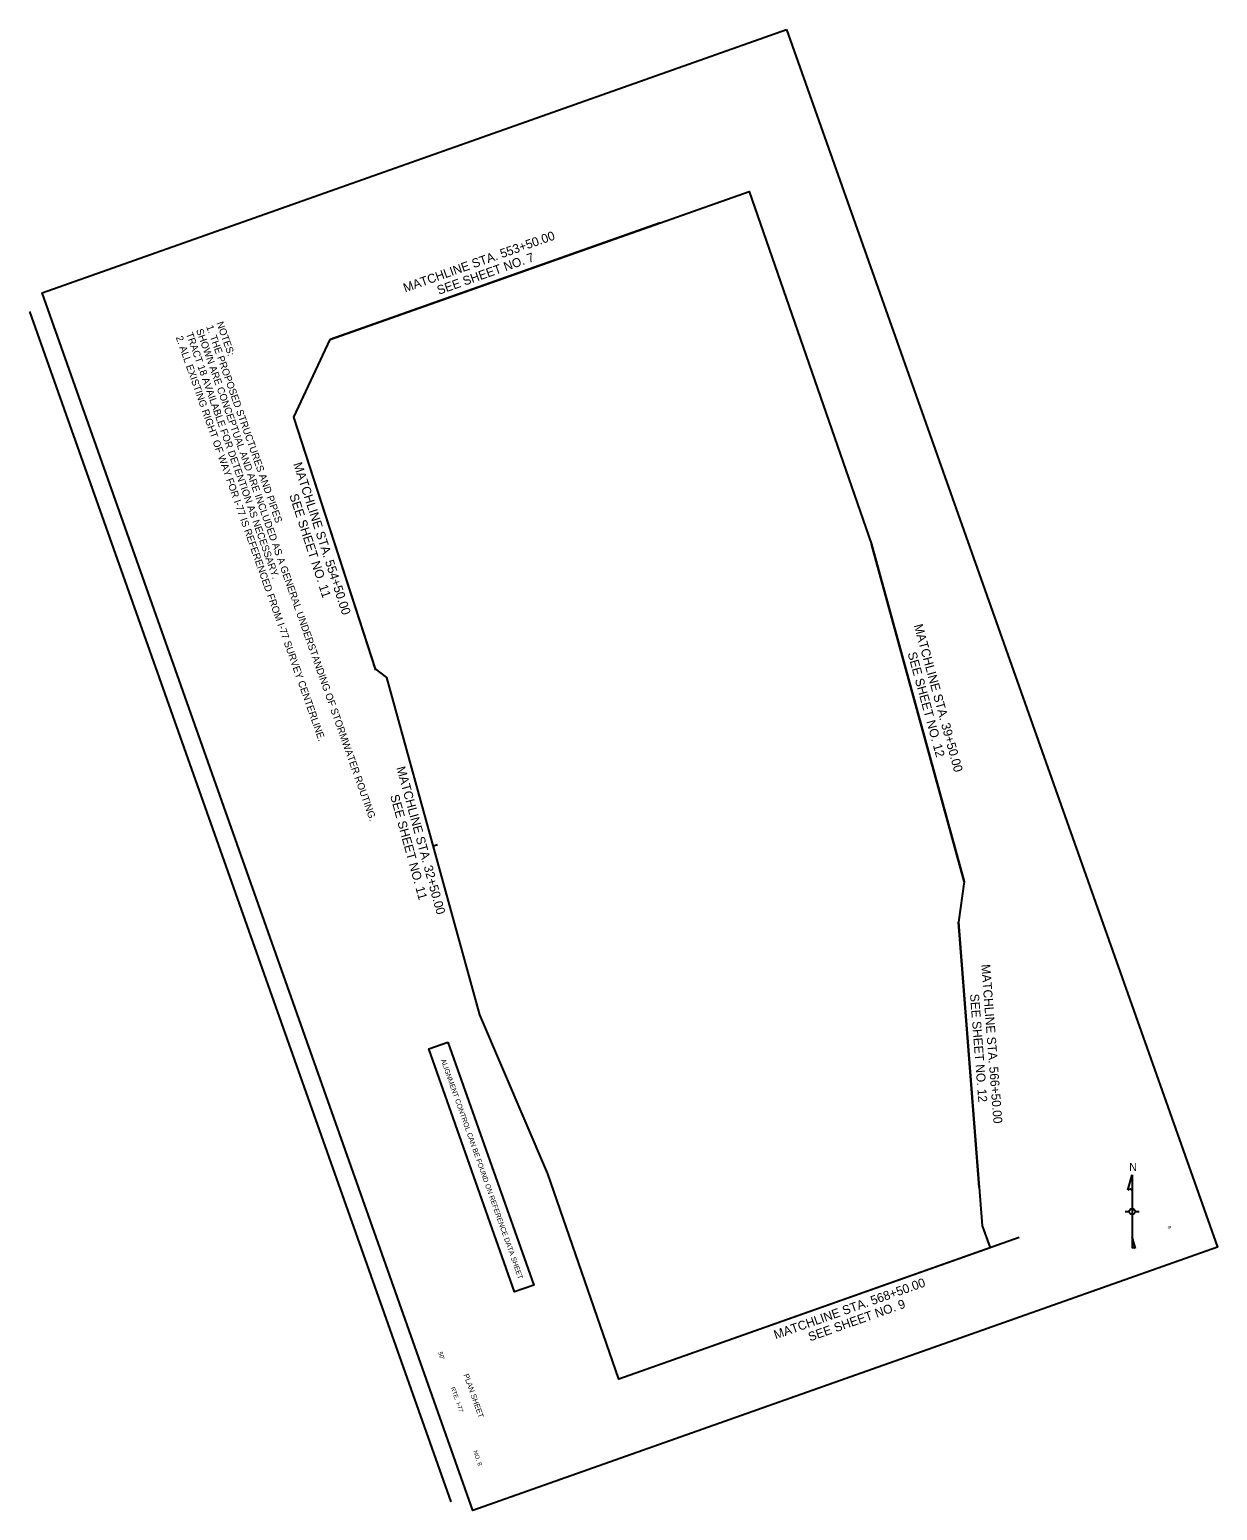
# Model space of a CAD drawing. Extents: x 2005048 to 2006703, y 1136071 to 1138135.
import ezdxf

# ---------------------------------------------------------------- set-up
doc = ezdxf.new("R2010")
doc.units = 0
for name, color, linetype in [('North Arrow', 7, 'Continuous'), ('RD_SHT_IplotShp', 7, 'Continuous'), ('RD_SHT_MatchLine', 7, 'Continuous'), ('RD_SHT_Misc1', 7, 'Continuous'), ('RD_SHT_ShtClip', 7, 'Continuous'), ('RD_SHT_TX', 7, 'Continuous')]:
    doc.layers.add(name, color=color, linetype=linetype)

msp = doc.modelspace()

# ---------------------------------------------------------------- linework, layer by layer
at = {"layer": 'North Arrow'}
for p, q in [((2006577.9, 1136517.4), (2006583.8, 1136538.4)), ((2006583.8, 1136538.4), (2006583.8, 1136516.2)), ((2006583.8, 1136538.4), (2006583.8, 1136436.2)), ((2006574.1, 1136487.3), (2006579.8, 1136487.3)), ((2006587.9, 1136487.3), (2006593.5, 1136487.3)), ((2006583.8, 1136452), (2006583.8, 1136436.2)), ((2006588.4, 1136435.9), (2006583.8, 1136452))]:
    msp.add_line(p, q, dxfattribs=at)
msp.add_circle((2006583.8, 1136487.3), 4.02, dxfattribs=at)
for centre, radius, start, end in [((2006580.5, 1136514.9), 3.59, 22.3707, 136.1387), ((2006586, 1136433.7), 3.3, 43.3397, 130.5607)]:
    msp.add_arc(centre, radius, start, end, dxfattribs=at)
at = {"layer": 'RD_SHT_IplotShp'}
msp.add_line((2005616.2, 1136998.3), (2005610.3, 1136996.7), dxfattribs=at)
msp.add_lwpolyline([(2006102.2, 1138134.7), (2006702.6, 1136437.7), (2005665.5, 1136070.9), (2005065.2, 1137767.8)], close=True, dxfattribs=at)
at = {"layer": 'RD_SHT_MatchLine'}
for p, q in [((2005926.3, 1137865.4), (2005466.7, 1137702.8)), ((2005530, 1137242), (2005415.7, 1137594.3)), ((2006349.9, 1136947.4), (2006220.5, 1137417.4)), ((2005675, 1136761.7), (2005545.6, 1137231.7)), ((2006370.6, 1136521.5), (2006341.8, 1136890.8)), ((2006426.6, 1136451.3), (2005967, 1136288.7))]:
    msp.add_line(p, q, dxfattribs=at)
at = {"layer": 'RD_SHT_ShtClip'}
msp.add_lwpolyline([(2005466.7, 1137702.8), (2006050.1, 1137909.2), (2006220.5, 1137417.4), (2006349.9, 1136947.4), (2006341.8, 1136890.8), (2006374.8, 1136467.3), (2006385.9, 1136436.9), (2005868.7, 1136253.9), (2005769.8, 1136540.1), (2005675, 1136761.7), (2005545.6, 1137231.7), (2005529.5, 1137243.8), (2005415.7, 1137594.3)], close=True, dxfattribs=at)
at = {"layer": 'RD_SHT_TX'}
msp.add_line((2005047.9, 1137741.9), (2005634.8, 1136082.7), dxfattribs=at)
msp.add_line((2005047.9, 1137741.9), (2005634.8, 1136082.7), dxfattribs=at)
msp.add_lwpolyline([(2005630.5, 1136723.4), (2005750.3, 1136384.8), (2005723.5, 1136375.4), (2005603.8, 1136714)], close=True, dxfattribs=at)

# ---------------------------------------------------------------- texts
at = {"layer": 'North Arrow'}
msp.add_text('N', height=11.1, dxfattribs=at).set_placement((2006579.8, 1136543.9))
at = {"layer": 'RD_SHT_MatchLine'}
for s, rotation, p in [('MATCHLINE STA. 553+50.00', 19.482, (2005571, 1137768.3)), ('SEE SHEET NO. 7', 19.482, (2005618, 1137765)), ('MATCHLINE STA. 554+50.00', 287.9765, (2005415, 1137529.4)), ('SEE SHEET NO. 11', 287.9765, (2005409.5, 1137485.5)), ('MATCHLINE STA. 39+50.00', 285.3889, (2006279.6, 1137304.3)), ('SEE SHEET NO. 12', 285.3889, (2006270.9, 1137265.4)), ('MATCHLINE STA. 32+50.00', 285.3889, (2005558.7, 1137105.9)), ('SEE SHEET NO. 11', 285.3889, (2005550, 1137066.8)), ('MATCHLINE STA. 566+50.00', 274.4504, (2006373.5, 1136831.5)), ('SEE SHEET NO. 12', 274.4504, (2006357.9, 1136790.3)), ('MATCHLINE STA. 568+50.00', 19.482, (2006087.2, 1136309.2)), ('SEE SHEET NO. 9', 19.482, (2006135.1, 1136306.3))]:
    msp.add_text(s, height=12.5, rotation=rotation, dxfattribs=at).set_placement(p)
at = {"layer": 'RD_SHT_Misc1'}
for s, p in [('SHOWN ARE CONCEPTUAL AND ARE INCLUDED AS A GENERAL UNDERSTANDING OF STORMWATER ROUTING.  ', (2005279.6, 1137715.8)), ('1. THE PROPOSED STRUCTURES AND PIPES ', (2005293.7, 1137720.8)), ('NOTES:', (2005307.9, 1137725.8)), ('2. ALL EXISTING RIGHT OF WAY FOR I-77 IS REFERENCED FROM I-77 SURVEY CENTERLINE.', (2005251.3, 1137705.8)), ('TRACT 18 AVAILABLE FOR DETENTION AS NECESSARY. ', (2005265.5, 1137710.8))]:
    msp.add_text(s, height=10, rotation=289.482, dxfattribs=at).set_placement(p)
at = {"layer": 'RD_SHT_TX'}
for s, height, p in [('ALIGNMENT CONTROL CAN BE FOUND ON REFERENCE DATA SHEET', 7, (2005620.5, 1136698.8)), ('8', 4.5, (2006633.1, 1136466.2)), ("50'", 6, (2005616.9, 1136290.8)), ('PLAN SHEET', 7.5, (2005652.2, 1136259.8)), ('RTE.', 6, (2005634.3, 1136241.7)), ('I-77', 6, (2005641.9, 1136220.2)), ('NO.', 6, (2005665.6, 1136153.2)), ('8', 6, (2005671.4, 1136136.9))]:
    msp.add_text(s, height=height, rotation=289.482, dxfattribs=at).set_placement(p)

doc.saveas('drawing.dxf')
